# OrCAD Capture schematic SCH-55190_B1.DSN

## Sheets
1 QSPI & LDO: size C; title: M2-NOR-FLASH; rev: B1; company: NXP Semiconductors; note: SCH-55190 PDF: SPF-55190; note: 6501 William Cannon Drive West; note: Austin, TX 78735-8598
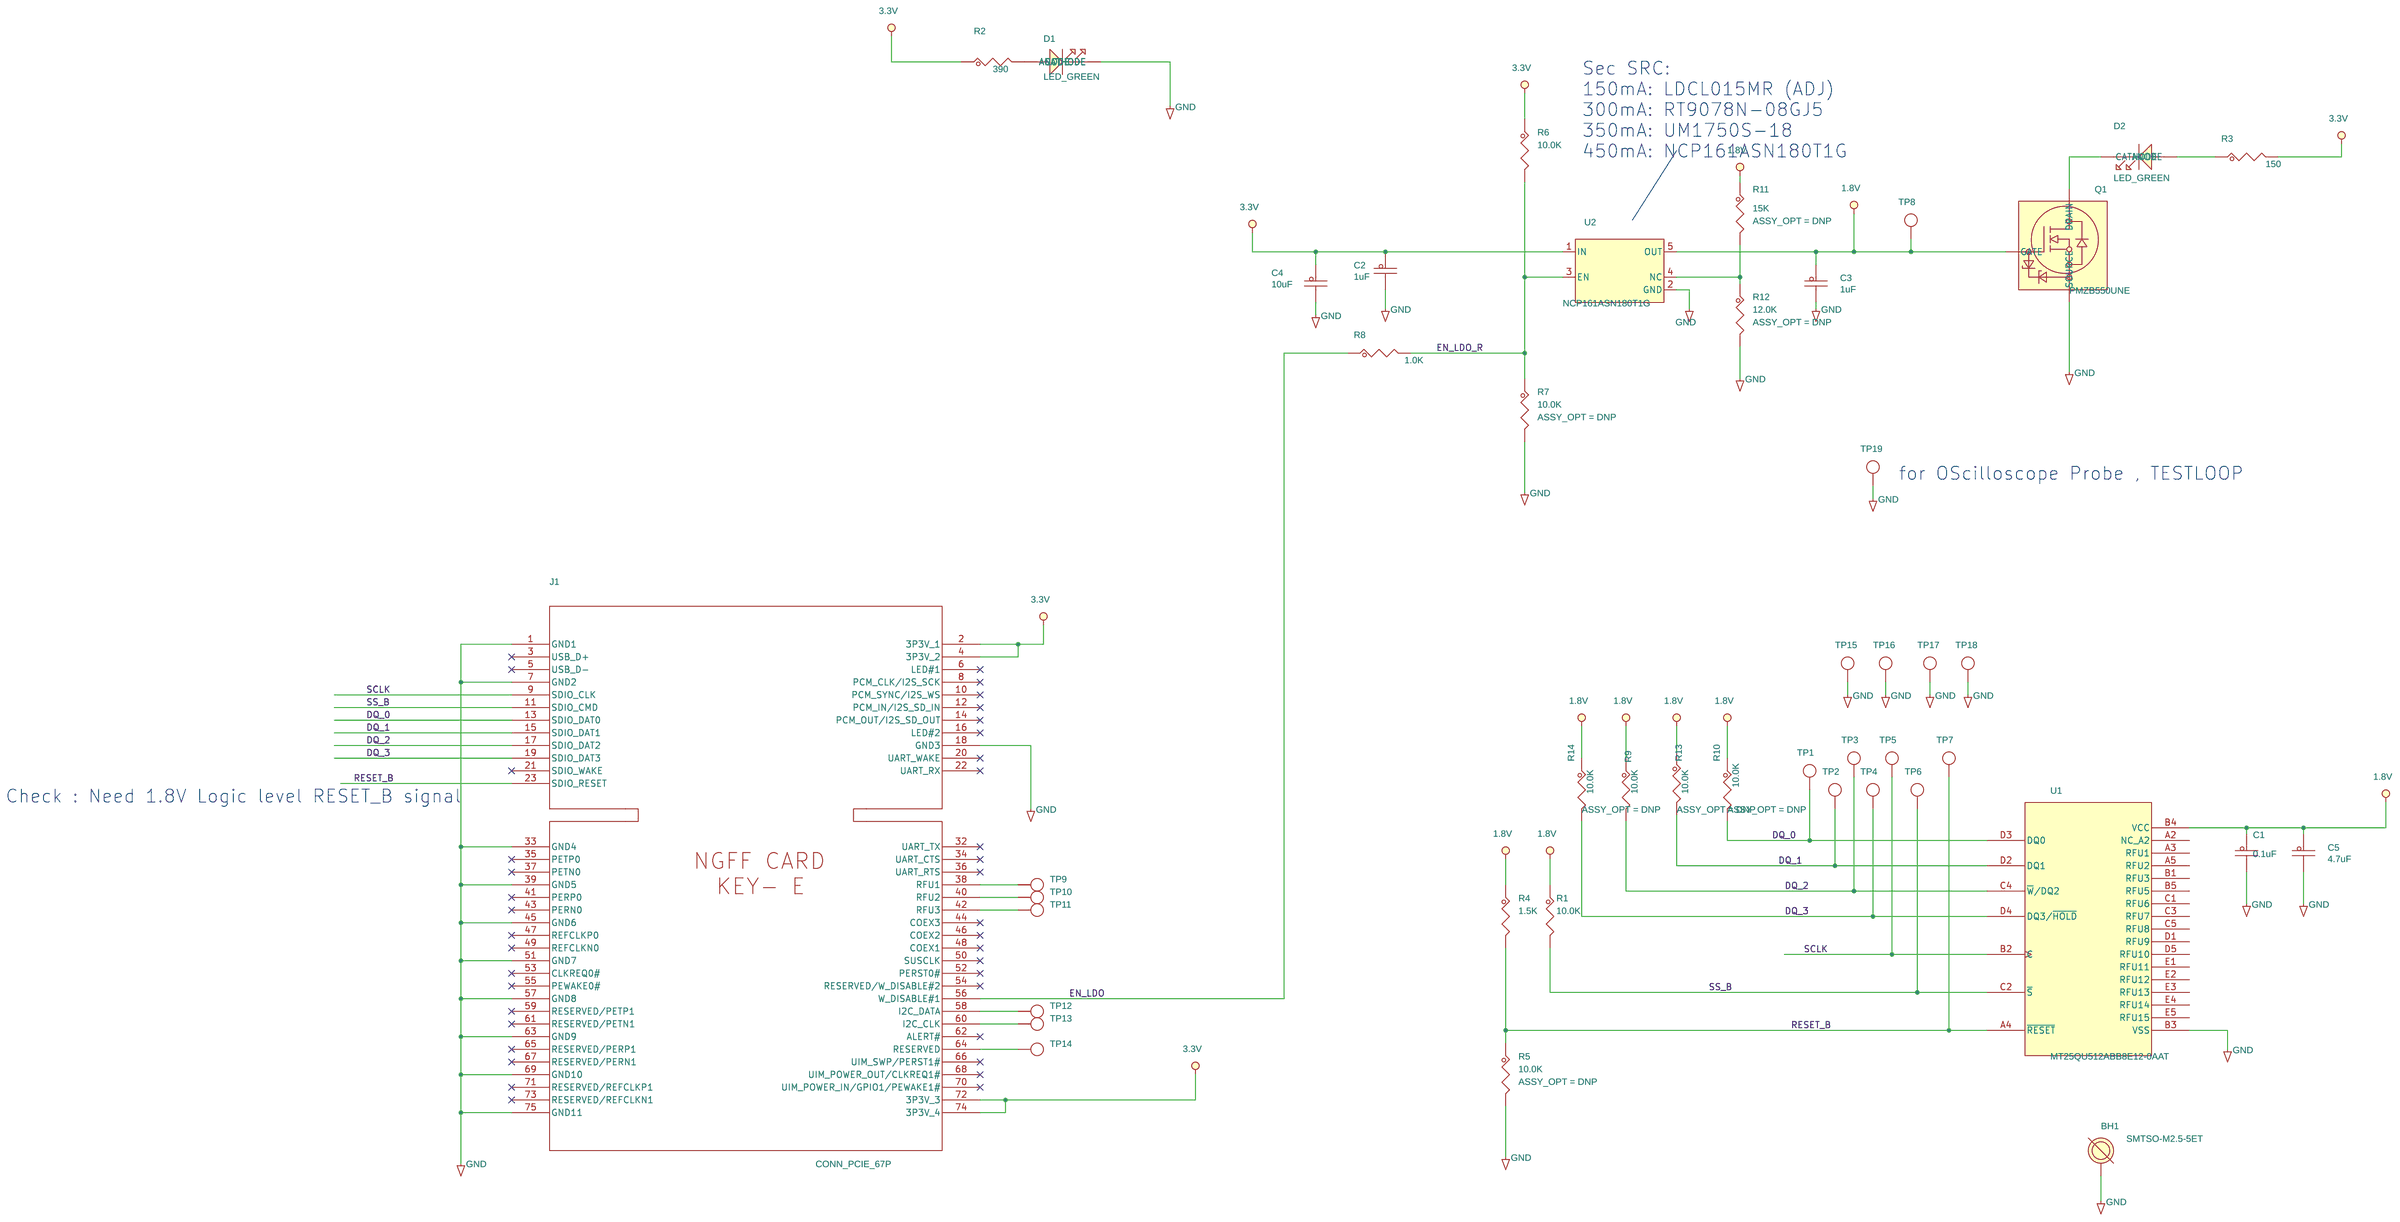
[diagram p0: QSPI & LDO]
2 01 Title Page & Notes: company: Freescale Semiconductor
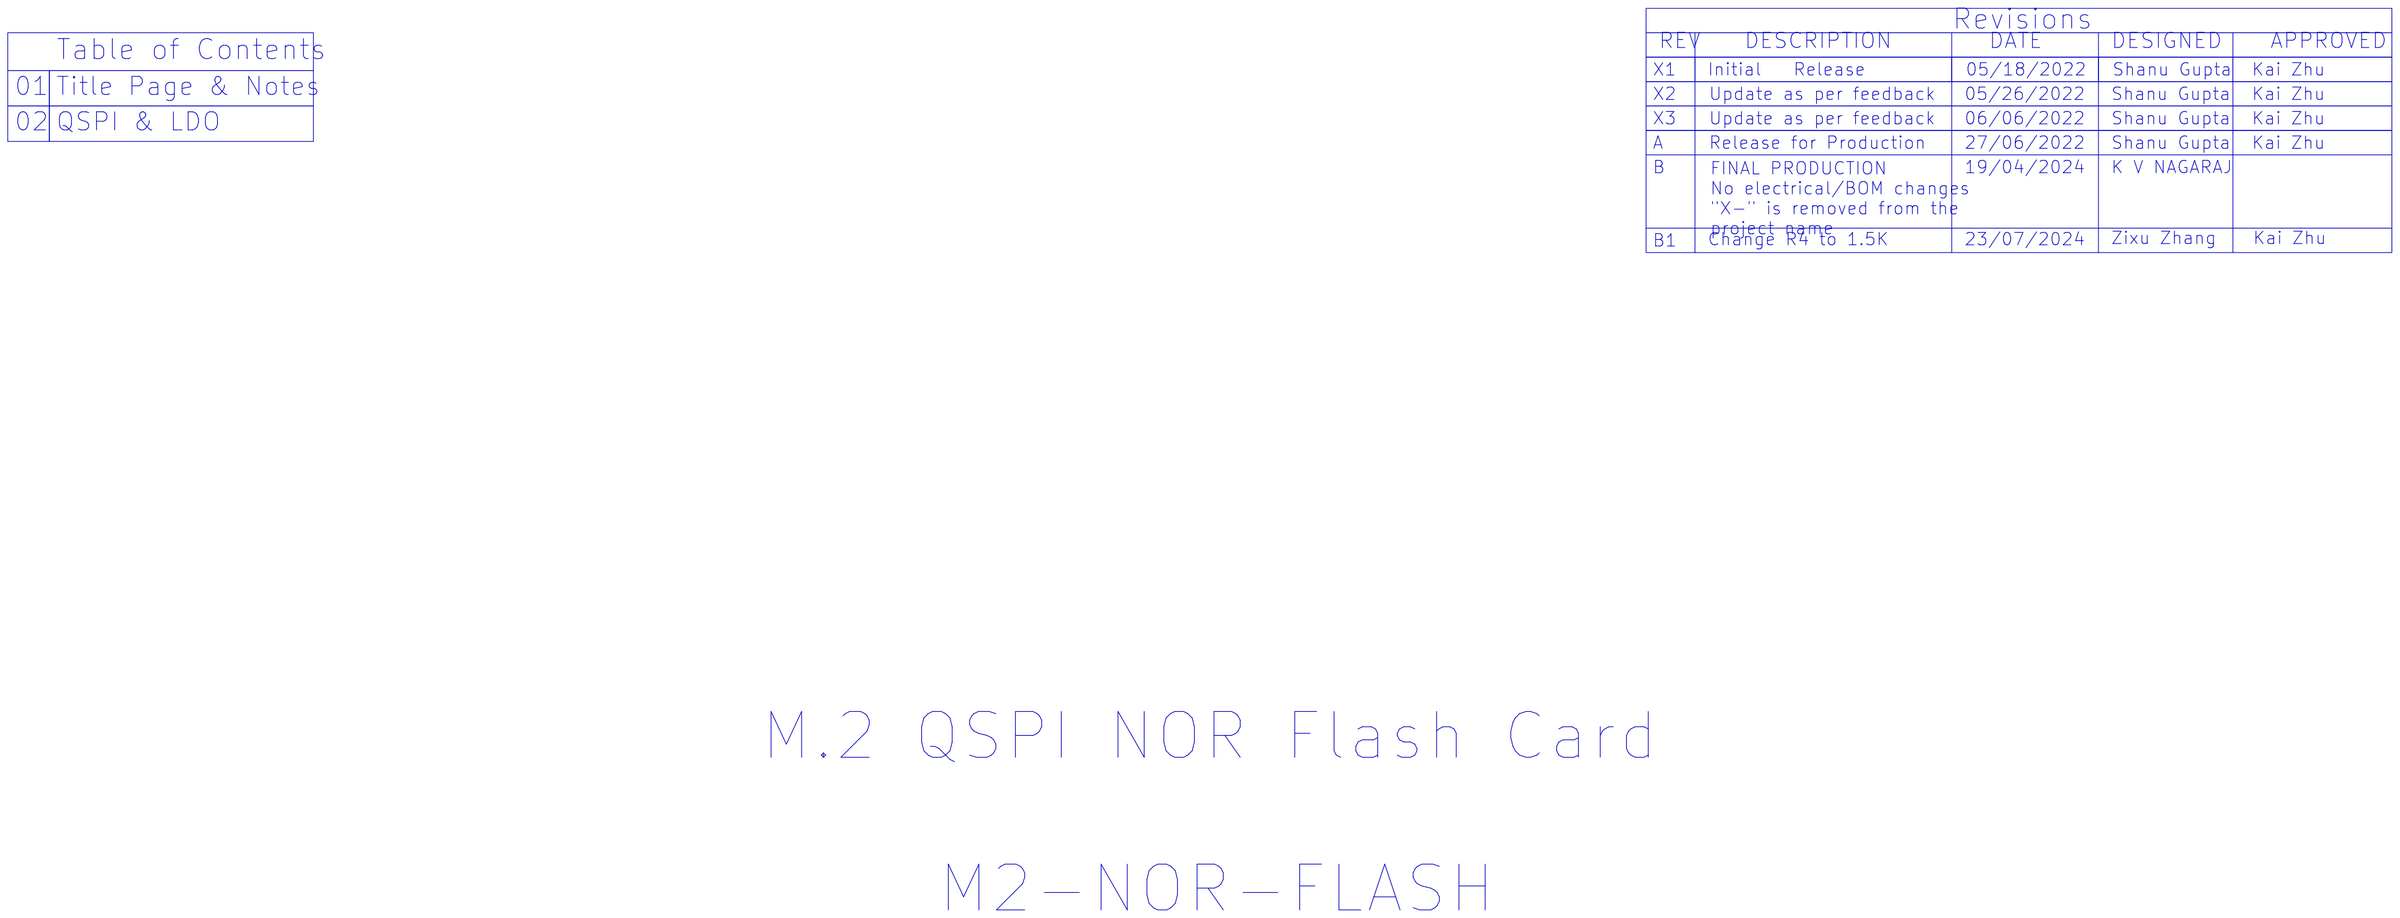
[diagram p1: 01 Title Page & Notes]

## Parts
BH1  SMTSO-M2.5-5ET  [mh244-166t_202h]
C1  0.1uF  [CC0402_25]
C2  1uF  [CC0603_OV]
C3  1uF  [CC0603_OV]
C4  10uF  [CC0603_OV]
C5  4.7uF  [CC0603_OV]
D1  LED_GREEN  [LED_0603]
D2  LED_GREEN  [LED_0603]
J1  CONN_PCIE_67P  [con_edge_67p_0p5_sm]
Q1  PMZB550UNE  [dfn10106b]
R1  10.0K  [RC0402_25]
R2  390  [RC0402_25]
R3  150  [RC0402_25]
R4  1.5K  [RC0402_25]
R5  10.0K  [RC0402_25]
R6  10.0K  [RC0402_25]
R7  10.0K  [RC0402_25]
R8  1.0K  [RC0402_25]
R9  10.0K  [RC0402_25]
R10  10.0K  [RC0402_25]
R11  15K  [RC0402_25]
R12  12.0K  [RC0402_25]
R13  10.0K  [RC0402_25]
R14  10.0K  [RC0402_25]
TP1  TPAD_020  [tpad_020]
TP2  TPAD_020  [tpad_020]
TP3  TPAD_020  [tpad_020]
TP4  TPAD_020  [tpad_020]
TP5  TPAD_020  [tpad_020]
TP6  TPAD_020  [tpad_020]
TP7  TPAD_020  [tpad_020]
TP8  TPAD_050  [TPAD_050]
TP9  TPAD_020  [tpad_020]
TP10  TPAD_020  [tpad_020]
TP11  TPAD_020  [tpad_020]
TP12  TPAD_020  [tpad_020]
TP13  TPAD_020  [tpad_020]
TP14  TPAD_020  [tpad_020]
TP15  TPAD_050  [TPAD_050]
TP16  TPAD_050  [TPAD_050]
TP17  TPAD_050  [TPAD_050]
TP18  TPAD_050  [TPAD_050]
TP19  TESTLOOP  [TEST_PIN_TP107]
U1  MT25QU512ABB8E12-0AAT  [pbga24_1_6x8mm]
U2  NCP161ASN180T1G  [SOT-23-5]

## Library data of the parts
BH1 = MOUNT_HOLE: FASTENER, STANDOFF M2.5 ROUND FEMALE OD CS L5.13MM; AGILE_PN: 280-77749; CAD_APPROVED: Yes; HEIGHT: 5.13MM; MFG_NAME01: SHENZHEN SINHOO SCIENCE TECHNOLOGY DEVELOPMENT CO.,LTD; ROHS: Yes
C1 = CAP_NP: CAP CER 0.1uF 50V 10% X7R AEC-Q200 0402; AGILE_PN: 150-79461; CAD_APPROVED: Yes; FPLIST: CC0402_25,CC0402_HD,0402_CC,CC0402_18; HEIGHT: 0.55MM; MFG_NAME01: MURATA; MFG_PN01: GCM155R71H104KE02D; PRIORITY_PN: 021-00196; Package Size: 0402; ROHS: Yes; Rated Voltage: 50V; Temp Range: -55C to +125C; Tolerance: 10%; VOLTAGE: 50V
C2 C3 = CAP_NP: CAP CER 1uF 16V 10% X7R 0603; AGILE_PN: 150-79460; CAD_APPROVED: Yes; FPLIST: CC0603_OV,CC0603,0603_CC; HEIGHT: 0.9 MM; MFG_NAME01: TDK; MFG_PN01: C1608X7R1C105K080AC; Package Size: 0603; ROHS: Yes; Rated Voltage: 16V; Temp Range: -55C to +125C; Tolerance: 10%; VOLTAGE: 16V
C4 = CAP_NP: CAP CER 10uF 10V 10% X7R 0603; AGILE_PN: 150-81133; CAD_APPROVED: Yes; FPLIST: CC0603_OV,CC0603,0603_cc_tol; HEIGHT: 1.0MM; MFG_NAME01: MURATA; MFG_PN01: GRM188Z71A106KA73D; Package Size: 0603 (1608 metric); Package Type: SMD/SMT; ROHS: Yes; Rated Voltage: 10V; Temp Range: -55C to +125C; Tolerance: 10%; VOLTAGE: 10V
C5 = CAP_NP: CAP CER 4.7uF 6.3V 10% X7R 0603; AGILE_PN: 150-79337; CAD_APPROVED: Yes; FPLIST: CC0603_OV,CC0603,0603_CC; HEIGHT: 0.95 MM; MFG_NAME01: SAMSUNG; MFG_PN01: CL10B475KQ8NQNC; Package Size: 0603; Package Type: 7"reel; ROHS: Yes; Rated Voltage: 6.3V; Temp Range: -55C to +125C; Tolerance: 10%; VOLTAGE: 6.3V
D1 D2 = LED: LED GRN SGL 30MA SMT 0603; AGILE_PN: 370-75143; CAD_APPROVED: Yes; HEIGHT: 1.1mm; MFG_NAME01: KINGBRIGHT; MFG_PN01: AP1608MGC
J1 = PCIEXPRESS_CONN67P_A: CON 67 PCI EXPRESS M.2 CRD KEY- E EDGE SMT 0.5MM AU NO PART TO ORDER; AGILE_PN: 211-80198; CAD_APPROVED: Yes; HEIGHT: 0.8MM; MFG_NAME01: N/A - NO PART TO ORDER; MFG_PN01: N/A - No Part to Order; ROHS: Yes
Q1 = NMOS_NX3008NBK: TRAN NMOS FET 30V 590mA 0.55OHM DFN1006B; 3D_Mechanical_Footprint_File: ftp://fcl.am.freescale.net/ALLEGRO/step/dfn10106b.STEP; AGILE_PN: 480-79783; CAD_APPROVED: Yes; HEIGHT: 0.4MM; MFG_NAME01: NEXPERIA; MFG_PN01: PMZB550UNEYL; ROHS: Yes
R1 R6 R9 = RES: RES MF 10.0K 1/16W 1% AEC-Q200 0402; AGILE_PN: 470-75416; CAD_APPROVED: Yes; FPLIST: RC0402_25,RC0402_HD,0402_CC; HEIGHT: 0.4MM; MFG_NAME01: KOA SPEER; MFG_PN01: RK73H1ETTP1002F; ROHS: Yes; Temp Range: –55 °C to +155 °C; Tolerance: 1%
R2 = RES: RES MF 390 OHM 1/16W 1% 0402; AGILE_PN: 470-76476; CAD_APPROVED: Yes; FPLIST: RC0402_25,RC0402_HD,0402_CC; HEIGHT: 0.4MM; MFG_NAME01: THYE MING TECH CO LTD; MFG_PN01: CR02FL6--390R; ROHS: Yes; Tolerance: 1%
R3 = RES: RES MF 150 OHM 1/16W 1% 0402; AGILE_PN: 470-75353; CAD_APPROVED: Yes; FPLIST: RC0402_25,RC0402_HD,0402_CC; HEIGHT: 0.4MM; MFG_NAME01: NIC COMPONENTS CORP; MFG_PN01: NRCL04F1500TRF; ROHS: Yes; Tolerance: 1%
R4 = RES: RES MF 1.5K 1/16W 5% 0402; AGILE_PN: 470-76303; CAD_APPROVED: Yes; HEIGHT: 0.40; MFG_NAME01: VENKEL COMPANY; MFG_PN01: CR0402-16W-152JT; ROHS: Yes; Tolerance: 5%
R5 R7 R10 R13 R14 = RES: RES MF 10.0K 1/16W 1% AEC-Q200 0402; AGILE_PN: 470-75416; ASSY_OPT: DNP; CAD_APPROVED: Yes; FPLIST: RC0402_25,RC0402_HD,0402_CC; HEIGHT: 0.4MM; MFG_NAME01: KOA SPEER; MFG_PN01: RK73H1ETTP1002F; ROHS: Yes; Temp Range: –55 °C to +155 °C; Tolerance: 1%
R8 = RES: RES MF 1.0K 1/16W 1% 0402; AGILE_PN: 470-76037; CAD_APPROVED: Yes; FPLIST: RC0402_25,RC0402_HD,RC0402_X2,0402_CC; HEIGHT: 0.4MM; MFG_NAME01: VISHAY; MFG_PN01: CRCW04021K00FKEDC; ROHS: Yes; Tolerance: 1%
R11 = RES: RES MF 15.0K 1/16W 1% 0402; AGILE_PN: 470-76066; ASSY_OPT: DNP; CAD_APPROVED: Yes; FPLIST: RC0402_25,RC0402_HD,0402_CC; HEIGHT: 0.4 MM; MFG_NAME01: NIC COMPONENTS CORP; MFG_PN01: NRCL04F1502TRF; ROHS: Yes; Tolerance: 1%
R12 = RES: RES MF 12.0K 1/16W 1% 0402; AGILE_PN: 470-76083; ASSY_OPT: DNP; CAD_APPROVED: Yes; FPLIST: RC0402_25,RC0402_HD,0402_CC; HEIGHT: 0.4 MM; MFG_NAME01: BOURNS; MFG_PN01: CR0402-FX-1202GLF; ROHS: Yes; Tolerance: 1%
TP1-TP7 TP9-TP14 = TestLoop: TEST POINT PAD 0.5MM DIA SMT, NO PART TO ORDER; AGILE_PN: 211-77484; CAD_APPROVED: Yes; HEIGHT: 0.1MM; ROHS: Yes
TP8 TP15-TP18 = TestLoop: TEST POINT PAD 50MIL DIA SMT, NO PART TO ORDER; AGILE_PN: 211-76644; CAD_APPROVED: Yes; HEIGHT: 0.1MM; MFG_NAME01: NOTACOMPONENT; MFG_PN01: NOTACOMPONENT; ROHS: Yes
TP19 = TestLoop: TEST POINT PAD SIZE 4.7MM X 3.5MM SN; 3D_Mechanical_Footprint_File: ftp://fcl.am.freescale.net/ALLEGRO/step/TEST_PIN_TP107.STEP; AGILE_PN: 211-30043; CAD_APPROVED: Yes; HEIGHT: 2.286MM; MFG_NAME01: KEYSTONE ELECTRONICS; MFG_PN01: 5016; ROHS: Yes; Temp Range: -50°C to +146°C
U1 = MT25QU512ABA8E12-BGA24_A: IC MEM FLASH SERIAL NOR 512MB 166/90MHZ 1.7-2V AEC-Q100 T-PBGA24; AGILE_PN: 342-00720; CAD_APPROVED: Yes; HEIGHT: 1.2MM; MFG_NAME01: MICRON; ROHS: Yes; Temp Range: -40C to +105C; VOLTAGE: 1.7-2V
U2 = NCP161ASN180T1G: IC VREG LDO FIXED 1.8V 450mA 1.9-5.5V SOT23-5; 3D_Mechanical_Footprint_File: ftp://fcl.am.freescale.net/ALLEGRO/step/sot-23-5.STEP; AGILE_PN: 315-83463; CAD_APPROVED: Yes; HEIGHT: 1.3 MM; MFG_NAME01: ONSEMI; ROHS: Yes; Temp Range: -40°C ~ 125°C (TJ); VOLTAGE: 1.9-5.5V

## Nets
1.8V: C1.1 C3.1 C5.1 Q1.1(GATE) R1.1 R4.1 R9.1 R10.1 R11.1 R13.1 R14.1 TP8.1(Pin1) U1.B4(VCC) U2.5(OUT)
3.3V: C2.1 C4.1 J1.2(3P3V_1) J1.4(3P3V_2) J1.72(3P3V_3) J1.74(3P3V_4) R2.1 R3.2 R6.1 U2.1(IN)
GND: BH1.1 C1.2 C2.2 C3.2 C4.2 C5.2 D1.C(CATHODE) J1.1(GND1) J1.7(GND2) J1.18(GND3) J1.33(GND4) J1.39(GND5) J1.45(GND6) J1.51(GND7) J1.57(GND8) J1.63(GND9) J1.69(GND10) J1.75(GND11) Q1.2(SOURCE) R5.2 R7.2 R12.2 TP15.1(Pin1) TP16.1(Pin1) TP17.1(Pin1) TP18.1(Pin1) TP19.1(Pin1) U1.B3(VSS) U2.2(GND)
DQ_0: J1.13(SDIO_DAT0) R10.2 TP1.1(Pin1) U1.D3(DQ0)
DQ_1: J1.15(SDIO_DAT1) R13.2 TP2.1(Pin1) U1.D2(DQ1)
DQ_2: J1.17(SDIO_DAT2) R9.2 TP3.1(Pin1) U1.C4(~{W}/DQ2)
DQ_3: J1.19(SDIO_DAT3) R14.2 TP4.1(Pin1) U1.D4(DQ3/~{HOLD})
EN_LDO: J1.56(W_DISABLE#1) R8.1
EN_LDO_R: R6.2 R7.1 R8.2 U2.3(EN)
RESET_B: J1.23(SDIO_RESET) R4.2 R5.1 TP7.1(Pin1) U1.A4(~{RESET})
SCLK: J1.9(SDIO_CLK) TP5.1(Pin1) U1.B2(C)
SS_B: J1.11(SDIO_CMD) R1.2 TP6.1(Pin1) U1.C2(~{S})
N30624074: J1.38(RFU1) TP9.1(Pin1)
N30624085: J1.40(RFU2) TP10.1(Pin1)
N30624096: J1.42(RFU3) TP11.1(Pin1)
N30624128: J1.58(I2C_DATA) TP12.1(Pin1)
N30624137: J1.60(I2C_CLK) TP13.1(Pin1)
N30624146: J1.64(RESERVED) TP14.1(Pin1)
N30625327: D2.C(CATHODE) Q1.3(DRAIN)
N30627604: D2.A(ANODE) R3.1
N30628082: R11.2 R12.1 U2.4(NC)
N30631010: D1.A(ANODE) R2.2

Not connected (* = marked no-connect by the designer): J1 3(USB_D+)* 5(USB_D-)* 6(LED#1)* 8(PCM_CLK/I2S_SCK)* 10(PCM_SYNC/I2S_WS)* 12(PCM_IN/I2S_SD_IN)* 14(PCM_OUT/I2S_SD_OUT)* 16(LED#2)* 20(UART_WAKE)* 21(SDIO_WAKE)* 22(UART_RX)* 32(UART_TX)* 34(UART_CTS)* 35(PETP0)* 36(UART_RTS)* 37(PETN0)* 41(PERP0)* 43(PERN0)* 44(COEX3)* 46(COEX2)* 47(REFCLKP0)* 48(COEX1)* 49(REFCLKN0)* 50(SUSCLK)* 52(PERST0#)* 53(CLKREQ0#)* 54(RESERVED/W_DISABLE#2)* 55(PEWAKE0#)* 59(RESERVED/PETP1)* 61(RESERVED/PETN1)* 62(ALERT#)* 65(RESERVED/PERP1)* 66(UIM_SWP/PERST1#)* 67(RESERVED/PERN1)* 68(UIM_POWER_OUT/CLKREQ1#)* 70(UIM_POWER_IN/GPIO1/PEWAKE1#)* 71(RESERVED/REFCLKP1)* 73(RESERVED/REFCLKN1)*; U1 A2(NC) A3(RFU1) A5(RFU2) B1(RFU3) B5(RFU5) C1(RFU6) C3(RFU7) C5(RFU8) D1(RFU9) D5(RFU10) E1(RFU11) E2(RFU12) E3(RFU13) E4(RFU14) E5(RFU15)

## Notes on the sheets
sheet 1
- Sec SRC:
  150mA: LDCL015MR (ADJ)
  300mA: RT9078N-08GJ5
  350mA: UM1750S-18
  450mA: NCP161ASN180T1G
- for OScilloscope Probe , TESTLOOP
- Check : Need 1.8V Logic level RESET_B signal
sheet 2
- Revisions
- Table of Contents
- REV
- DESCRIPTION
- DATE
- DESIGNED
- APPROVED
- X1
- Initial
- Release
- 05/18/2022
- Shanu Gupta
- Kai Zhu
- 01
- Title Page & Notes
- X2
- Update as per feedback
- 05/26/2022
- Shanu Gupta
- Kai Zhu
- 02
- QSPI & LDO
- X3
- Update as per feedback
- 06/06/2022
- Shanu Gupta
- Kai Zhu
- A
- Release for Production
- 27/06/2022
- Shanu Gupta
- Kai Zhu
- B
- FINAL PRODUCTION
  No electrical/BOM changes
  "X-" is removed from the
  project name
- 19/04/2024
- K V NAGARAJ
- B1
- Change R4 to 1.5K
- 23/07/2024
- Zixu Zhang
- Kai Zhu
- M.2 QSPI NOR Flash Card
- M2-NOR-FLASH
